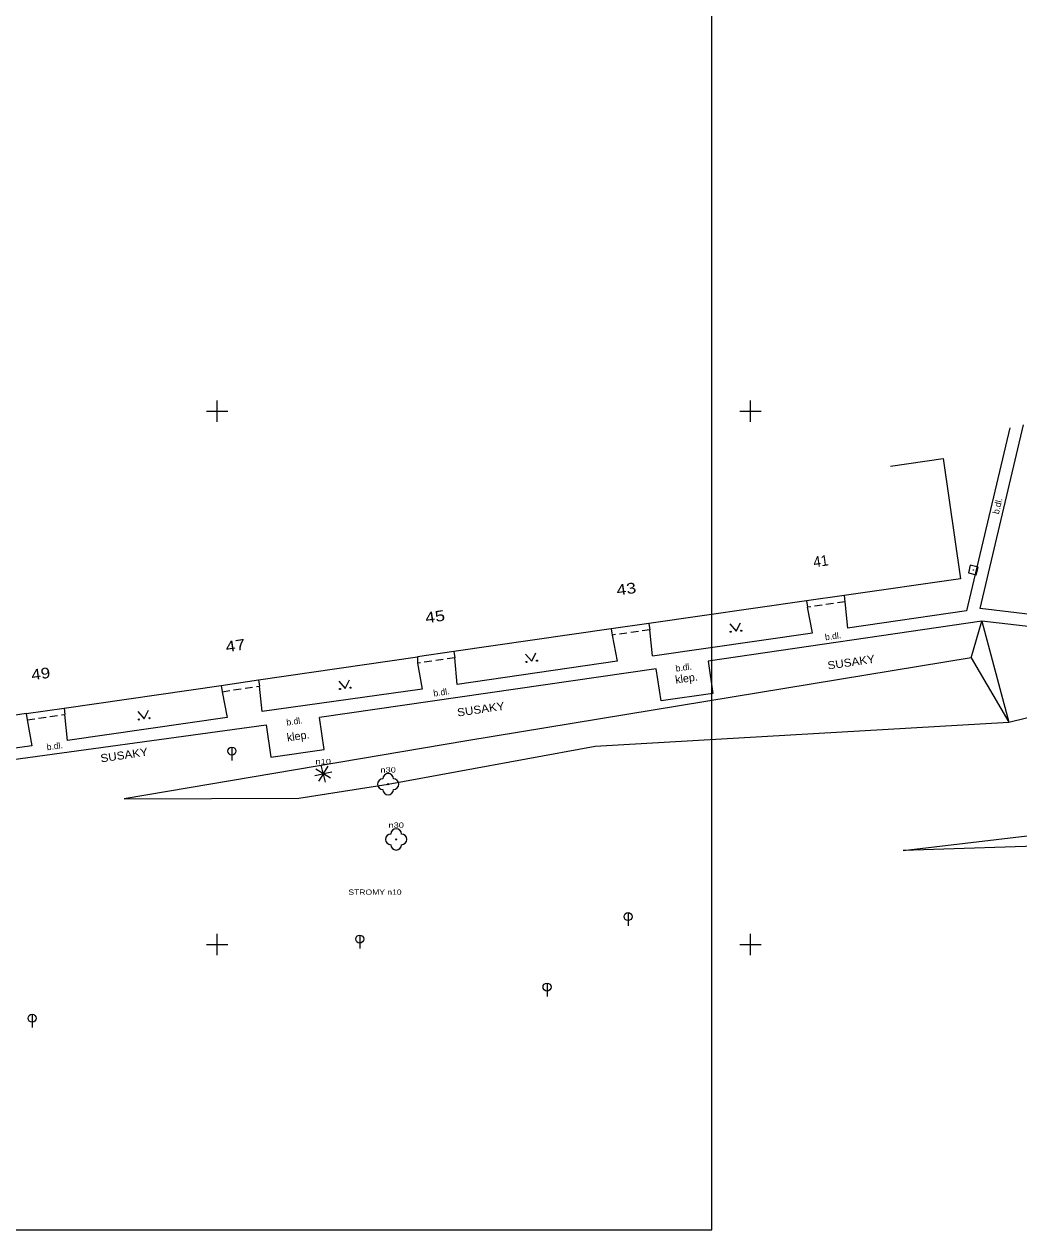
# Model space of a CAD drawing. Extents: x -670514 to -669423, y -1130798 to -1130123.
# Drawn here: x -670168.1 to -670074.8, y -1130676.8 to -1130563.7 of the extents above; entities that cross this region are included whole.
import ezdxf
from ezdxf.enums import TextEntityAlignment as Align

# ---------------------------------------------------------------- set-up
doc = ezdxf.new("R2010")
doc.units = 0
doc.header["$LTSCALE"] = 0.24
doc.linetypes.add('MEDIUM_DASHED', pattern=[4.5, 3, -1.5])
for name, color, linetype, lineweight in [('10', 7, 'Continuous', 13), ('14', 7, 'Continuous', 13), ('22', 7, 'Continuous', 13), ('26', 7, 'Continuous', 13), ('27', 7, 'Continuous', 13), ('36', 7, 'Continuous', 13), ('5', 7, 'Continuous', 13), ('60', 7, 'Continuous', 13), ('61', 7, 'Continuous', 13)]:
    doc.layers.add(name, color=color, linetype=linetype, lineweight=lineweight)
for name, color, linetype in [('40', 7, 'Continuous'), ('42', 7, 'Continuous'), ('44', 7, 'Continuous')]:
    doc.layers.add(name, color=color, linetype=linetype)

msp = doc.modelspace()

# ---------------------------------------------------------------- linework, layer by layer
at = {"layer": '10'}
for p, q in [((-670091.149, -1130617.879), (-670090.902, -1130620.363)), ((-670109.174, -1130622.94), (-670109.444, -1130620.501)), ((-670131.218, -1130623.644), (-670130.784, -1130626.077)), ((-670108.852, -1130624.181), (-670140.383, -1130628.739))]:
    msp.add_line(p, q, dxfattribs=at)
for points in [[(-670075.695, -1130601.575), (-670079.766, -1130618.729), (-670090.902, -1130620.363)], [(-670072.966, -1130619.156), (-670078.479, -1130618.498), (-670074.424, -1130601.288)], [(-670109.174, -1130622.94), (-670094.195, -1130620.804), (-670094.657, -1130618.389)], [(-670078.329, -1130619.694), (-670103.968, -1130623.45), (-670103.532, -1130626.472), (-670108.389, -1130627.18), (-670108.852, -1130624.181)], [(-670061.814, -1130621.579), (-670061.252, -1130625.602), (-670068.842, -1130626.633), (-670069.057, -1130624.227), (-670063.713, -1130623.417), (-670063.988, -1130621.346), (-670078.329, -1130619.694)], [(-670112.964, -1130621.007), (-670112.506, -1130623.459), (-670127.479, -1130625.636), (-670127.723, -1130623.143)], [(-670130.784, -1130626.077), (-670145.782, -1130628.162), (-670146.017, -1130625.788)], [(-670149.51, -1130626.308), (-670149.041, -1130628.719), (-670164.019, -1130630.883), (-670164.254, -1130628.44)], [(-670172.317, -1130633.088), (-670145.385, -1130629.413), (-670144.955, -1130632.446), (-670139.963, -1130631.722), (-670140.383, -1130628.739)], [(-670167.799, -1130628.949), (-670167.351, -1130631.398), (-670170.978, -1130631.881)]]:
    msp.add_lwpolyline(points, dxfattribs=at)
at = {"layer": '14'}
for p, q in [((-670079.335, -1130623.15), (-670078.329, -1130619.694)), ((-670078.329, -1130619.694), (-670075.797, -1130629.157)), ((-670079.335, -1130623.15), (-670126.584, -1130630.907)), ((-670079.335, -1130623.15), (-670075.797, -1130629.157))]:
    msp.add_line(p, q, dxfattribs=at)
for points in [[(-670114.569, -1130631.426), (-670075.797, -1130629.157), (-670061.252, -1130625.602), (-670030.686, -1130625.152)], [(-670126.584, -1130630.907), (-670158.691, -1130636.347), (-670142.341, -1130636.299), (-670133.965, -1130634.976), (-670114.569, -1130631.426)]]:
    msp.add_lwpolyline(points, dxfattribs=at)
msp.add_lwpolyline([(-670030.686, -1130625.152), (-670033.584, -1130634.335), (-670049.529, -1130638.513), (-670060.1, -1130639.57), (-670070.428, -1130640.693), (-670085.68, -1130641.204), (-670071.151, -1130639.47), (-670055.745, -1130636.915), (-670050.159, -1130636.075), (-670035.411, -1130631.719)], close=True, dxfattribs=at)
at = {"layer": '22'}
for p, q in [((-670140.081, -1130633.974), (-670140.737, -1130633.56)), ((-670140.055, -1130633.954), (-670140.227, -1130633.2)), ((-670139.613, -1130633.304), (-670140.027, -1130633.96)), ((-670140.007, -1130633.986), (-670139.253, -1130633.814)), ((-670140.841, -1130634.174), (-670140.087, -1130634.002)), ((-670140.067, -1130634.028), (-670140.481, -1130634.684)), ((-670140.039, -1130634.034), (-670139.867, -1130634.788)), ((-670139.357, -1130634.428), (-670140.013, -1130634.014))]:
    msp.add_line(p, q, dxfattribs=at)
for centre, radius in [((-670140.047, -1130633.994), 0.04), ((-670133.965, -1130634.976), 0.05), ((-670133.21, -1130640.155), 0.05)]:
    msp.add_circle(centre, radius, dxfattribs=at)
for centre, start, end in [((-670134.465, -1130634.976), 90, 270), ((-670133.965, -1130634.476), 0, 180), ((-670133.465, -1130634.976), 270, 90), ((-670133.965, -1130635.476), 180, 0), ((-670133.21, -1130639.655), 0, 180), ((-670133.71, -1130640.155), 90, 270), ((-670133.21, -1130640.655), 180, 0), ((-670132.71, -1130640.155), 270, 90)]:
    msp.add_arc(centre, 0.5, start, end, dxfattribs=at)
at = {"layer": '26'}
msp.add_lwpolyline([(-670079.581, -1130615.178), (-670078.852, -1130615.356), (-670078.674, -1130614.627), (-670079.402, -1130614.449)], close=True, dxfattribs=at)
msp.add_circle((-670079.1272, -1130614.9026), 0.02, dxfattribs=at)
at = {"layer": '27'}
for p, q in [((-670148.609, -1130631.496), (-670148.609, -1130632.746)), ((-670111.481, -1130647.017), (-670111.481, -1130648.267)), ((-670136.623, -1130649.121), (-670136.623, -1130650.371)), ((-670119.074, -1130653.617), (-670119.074, -1130654.867)), ((-670167.328, -1130656.544), (-670167.328, -1130657.794))]:
    msp.add_line(p, q, dxfattribs=at)
for centre in [(-670148.6086, -1130631.8711), (-670111.4806, -1130647.3921), (-670136.6226, -1130649.4961), (-670119.0736, -1130653.9921), (-670167.3276, -1130656.9191)]:
    msp.add_circle(centre, 0.375, dxfattribs=at)
at = {"layer": '36'}
for points in [[(-670101.927, -1130619.943), (-670101.359, -1130620.642), (-670100.932, -1130619.849)], [(-670121.098, -1130622.779), (-670120.508, -1130623.46), (-670120.106, -1130622.654)], [(-670138.573, -1130625.315), (-670137.983, -1130625.996), (-670137.581, -1130625.19)], [(-670157.413, -1130628.175), (-670156.823, -1130628.856), (-670156.421, -1130628.05)]]:
    msp.add_lwpolyline(points, dxfattribs=at)
for centre in [(-670101.8566, -1130620.6895), (-670100.8611, -1130620.5955), (-670121.0046, -1130623.5227), (-670120.0124, -1130623.3983), (-670138.4796, -1130626.0587), (-670137.4874, -1130625.9343), (-670157.3196, -1130628.9187), (-670156.3274, -1130628.7943)]:
    msp.add_circle(centre, 0.05, dxfattribs=at)
at = {"layer": '5'}
for p, q in [((-670086.879, -1130605.164), (-670081.93, -1130604.455)), ((-670081.93, -1130604.455), (-670080.314, -1130615.737)), ((-670094.743, -1130617.795), (-670094.657, -1130618.389)), ((-670091.235, -1130617.285), (-670091.149, -1130617.879)), ((-670109.529, -1130619.907), (-670109.444, -1130620.501)), ((-670113.049, -1130620.413), (-670112.964, -1130621.007)), ((-670127.808, -1130622.549), (-670127.723, -1130623.143)), ((-670131.218, -1130623.044), (-670131.218, -1130623.644)), ((-670149.598, -1130625.715), (-670149.51, -1130626.308)), ((-670146.105, -1130625.195), (-670146.017, -1130625.788)), ((-670164.339, -1130627.846), (-670164.254, -1130628.44)), ((-670167.884, -1130628.355), (-670167.799, -1130628.949))]:
    msp.add_line(p, q, dxfattribs=at)
at = {"layer": '5', "linetype": 'MEDIUM_DASHED'}
for p, q in [((-670091.149, -1130617.879), (-670094.657, -1130618.389)), ((-670109.444, -1130620.501), (-670112.964, -1130621.007)), ((-670127.723, -1130623.143), (-670131.218, -1130623.644)), ((-670149.51, -1130626.308), (-670146.017, -1130625.788)), ((-670167.799, -1130628.949), (-670164.254, -1130628.44))]:
    msp.add_line(p, q, dxfattribs=at)
at = {"layer": '5'}
for points in [[(-670080.314, -1130615.737), (-670091.235, -1130617.285), (-670094.743, -1130617.795), (-670109.529, -1130619.907), (-670113.049, -1130620.413), (-670127.808, -1130622.549), (-670131.218, -1130623.044)], [(-670167.884, -1130628.355), (-670171.699, -1130628.933), (-670173.314, -1130617.6)], [(-670149.598, -1130625.715), (-670146.105, -1130625.195), (-670131.218, -1130623.044)], [(-670167.884, -1130628.355), (-670164.339, -1130627.846), (-670149.598, -1130625.715)]]:
    msp.add_lwpolyline(points, dxfattribs=at)
at = {"layer": '60'}
msp.add_lwpolyline([(-670513.627, -1130676.756), (-670103.627, -1130676.756), (-670103.627, -1130389.756), (-670513.627, -1130389.756)], close=True, dxfattribs=at)
at = {"layer": '61'}
for p, q in [((-670151, -1130600), (-670149, -1130600)), ((-670150, -1130601), (-670150, -1130599)), ((-670101, -1130600), (-670099, -1130600)), ((-670100, -1130601), (-670100, -1130599)), ((-670150, -1130651), (-670150, -1130649)), ((-670100, -1130651), (-670100, -1130649)), ((-670151, -1130650), (-670149, -1130650)), ((-670101, -1130650), (-670099, -1130650))]:
    msp.add_line(p, q, dxfattribs=at)

# ---------------------------------------------------------------- texts
at = {"layer": '22'}
for s, width, p in [('n10', 1.3, (-670140.0475, -1130633.108)), ('n30', 1.3, (-670133.9645, -1130633.89)), ('n30', 1.3, (-670133.2095, -1130639.069)), ('STROMY n10', 1.2, (-670135.195, -1130645.349))]:
    msp.add_text(s, height=0.499, dxfattribs=dict(at, width=width)).set_placement(p, align=Align.CENTER)
at = {"layer": '40'}
for rotation, p in [(76.742, (-670076.5538, -1130608.9708)), (8.334, (-670092.228, -1130621.3936)), (8.225, (-670106.2274, -1130624.3293)), (8.225, (-670128.9314, -1130626.6593)), (8.225, (-670142.7054, -1130629.3853)), (7.77, (-670165.1756, -1130631.7065))]:
    msp.add_text('b.dl.', height=0.6, rotation=rotation, dxfattribs=at).set_placement(p, align=Align.CENTER)
at = {"layer": '42', "width": 1.1}
for p in [(-670090.5134, -1130623.9099), (-670125.2244, -1130628.3189), (-670158.6554, -1130632.6169)]:
    msp.add_text('SUSAKY', height=0.75, rotation=8.334, dxfattribs=at).set_placement(p, align=Align.CENTER)
at = {"layer": '42'}
for p in [(-670105.9521, -1130625.4139), (-670142.3511, -1130630.8299)]:
    msp.add_text('klep.', height=0.75, rotation=8.294, dxfattribs=at).set_placement(p, align=Align.CENTER)
at = {"layer": '44'}
for s, rotation, width, p in [('41', 8.272, 0.95, (-670093.3434, -1130614.5599)), ('43', 8.18, 1.25, (-670111.5771, -1130617.1708)), ('45', 8.259, 1.25, (-670129.5023, -1130619.7634)), ('47', 8.467, 1.25, (-670148.2121, -1130622.4758)), ('49', 8.171, 1.2, (-670166.4566, -1130625.1193))]:
    msp.add_text(s, height=1, rotation=rotation, dxfattribs=dict(at, width=width)).set_placement(p, align=Align.CENTER)

doc.saveas('drawing.dxf')
